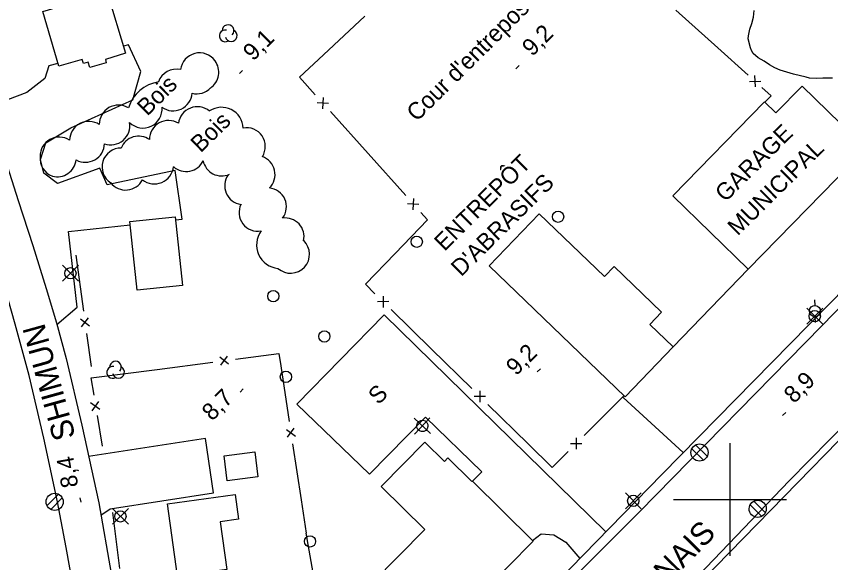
# Model space of a CAD drawing. Extents: x 381879 to 384696, y 5564785 to 5567594.
# Drawn here: x 383073.6 to 383217.8, y 5565788.8 to 5565885.6 of the extents above; entities that cross this region are included whole.
import ezdxf

# ---------------------------------------------------------------- set-up
doc = ezdxf.new("R2010")
doc.units = 0
for name, color, linetype in [('Niveau 1', 7, 'Continuous'), ('Niveau 19', 7, 'Continuous'), ('Niveau 21', 7, 'Continuous'), ('Niveau 22', 7, 'Continuous'), ('Niveau 3', 7, 'Continuous'), ('Niveau 31', 7, 'Continuous'), ('Niveau 36', 7, 'Continuous'), ('Niveau 37', 7, 'Continuous'), ('Niveau 44', 7, 'Continuous'), ('Niveau 52', 7, 'Continuous'), ('Niveau 57', 7, 'Continuous'), ('Niveau 61', 7, 'Continuous')]:
    doc.layers.add(name, color=color, linetype=linetype)

msp = doc.modelspace()

# ---------------------------------------------------------------- linework, layer by layer
at = {"layer": 'Niveau 1'}
msp.add_lwpolyline([(383218.14, 5565874.66), (383216.47, 5565874.7), (383215.25, 5565874.62), (383214.09, 5565874.7), (383213.49, 5565874.87), (383211.25, 5565875.41), (383208.91, 5565876.07), (383207.93, 5565876.49), (383207, 5565877.03), (383206.05, 5565877.7), (383204.99, 5565878.3), (383204.13, 5565879.06), (383203.81, 5565879.58), (383203.63, 5565880.05), (383203.23, 5565881.66), (383203.26, 5565882.19), (383203.53, 5565883.36), (383203.87, 5565884.34), (383204.17, 5565885.51), (383204.28, 5565886.66)], dxfattribs=at)
at = {"layer": 'Niveau 19'}
for points in [[(383101.78, 5565849.56), (383103, 5565849.69), (383101.74, 5565858.34), (383089.68, 5565855.78), (383088.39, 5565858.71), (383080.9, 5565855.98), (383078.47, 5565857.85), (383077.87, 5565860.26), (383078.84, 5565863.22), (383083.28, 5565865.88), (383094.22, 5565870.83), (383095.65, 5565875.88), (383093.49, 5565880.56), (383092.57, 5565880.32)], [(383080.98, 5565877.3), (383079.38, 5565876.88), (383078.66, 5565874.62), (383075.49, 5565872.15), (383072.04, 5565870.84), (383068.49, 5565869.87)], [(383080.77, 5565831.03), (383084.39, 5565834.08), (383082.86, 5565847.53), (383093.79, 5565848.7)], [(383203.21, 5565840.8), (383189.95, 5565827.06)], [(383181.1, 5565818.11), (383191.72, 5565808.31), (383191.72, 5565808.31)], [(383088.58, 5565797.23), (383090.24, 5565798.37), (383108.54, 5565801.18), (383107.11, 5565810.81), (383086.41, 5565807.65), (383086.41, 5565807.65)]]:
    msp.add_lwpolyline(points, dxfattribs=at)
at = {"layer": 'Niveau 21'}
for points in [[(383184, 5565797.8), (383216.28, 5565830.81), (383235.39, 5565850.47), (383275.62, 5565891.24), (383301.72, 5565917.97), (383337.3, 5565954.5), (383373.4, 5565991.3), (383408.2, 5566027), (383442.2, 5566061.7), (383475.8, 5566095.9)], [(383296.7, 5565891.1), (383280.8, 5565875), (383258.34, 5565852.55), (383246.6, 5565840.1), (383228.5, 5565821.6), (383210.51, 5565803.32), (383194.41, 5565786.56)], [(383067.06, 5565874.22), (383069.7, 5565866.2), (383073.9, 5565853), (383076.5, 5565845), (383078.9, 5565837.4), (383080.7, 5565831.3), (383082.4, 5565825), (383085.2, 5565813.2), (383088.2, 5565799.4), (383090.4, 5565786.9), (383093, 5565770), (383094.3, 5565760.4), (383096, 5565745.2), (383097.4, 5565731.2), (383098.3, 5565723.1), (383098.8, 5565719.9), (383099.7, 5565717.4), (383100.8, 5565715.9), (383101.9, 5565715.6)], [(383091, 5565706.2), (383090.4, 5565725), (383088.3, 5565748.4), (383085.9, 5565768.5), (383084.7, 5565777.6), (383083.7, 5565784.3), (383082.4, 5565791.5), (383080.9, 5565799.6), (383078.5, 5565810.9), (383075.9, 5565822), (383073.4, 5565831.1), (383070.89, 5565839.89)], [(383101.9, 5565715.6), (383103, 5565715.9), (383104.3, 5565716.6), (383105.6, 5565717.5), (383116.8, 5565728.8), (383135, 5565747.7), (383153.5, 5565766.7), (383172.3, 5565786.1), (383184, 5565797.8)]]:
    msp.add_lwpolyline(points, dxfattribs=at)
at = {"layer": 'Niveau 22'}
for points in [[(383156.53, 5565772.2), (383157.91, 5565773.63), (383187.98, 5565804.5), (383213.9, 5565830.88), (383244.88, 5565862.36), (383274.3, 5565892.74), (383302.87, 5565922), (383330.88, 5565950.51), (383359.91, 5565980.31), (383385.43, 5566006.36), (383414.56, 5566036.19)], [(383114.65, 5565703.59), (383143.11, 5565732.46), (383175.31, 5565765.37), (383202.42, 5565793.16), (383228.81, 5565820.22), (383246.73, 5565838.32)]]:
    msp.add_lwpolyline(points, dxfattribs=at)
at = {"layer": 'Niveau 3'}
for p, q in [((383113.12, 5565875.49), (383113.69, 5565876.06)), ((383162.1, 5565876.32), (383162.67, 5565876.89)), ((383165.86, 5565822.62), (383166.43, 5565823.19)), ((383113.22, 5565819.03), (383113.79, 5565819.6)), ((383209.3, 5565814.87), (383209.87, 5565815.44)), ((383085.06, 5565799.52), (383084.88, 5565800.3))]:
    msp.add_line(p, q, dxfattribs=at)
at = {"layer": 'Niveau 31'}
for points in [[(383078.31, 5565886.48), (383089.67, 5565889.91), (383092.94, 5565879.08), (383089.37, 5565878), (383089.54, 5565877.42), (383086.62, 5565876.56), (383086.34, 5565877.5), (383085.49, 5565877.25), (383085.27, 5565878.01), (383081.12, 5565876.8)], [(383224.12, 5565862.24), (383203.21, 5565840.8), (383189.87, 5565853.8), (383206.13, 5565870.48), (383208.14, 5565868.52), (383212.77, 5565873.24)], [(383101.72, 5565850.12), (383103.01, 5565837.96), (383095.02, 5565837.11), (383093.73, 5565849.27)], [(383181.44, 5565818.22), (383157.33, 5565841.4), (383166.2, 5565850.62), (383177.76, 5565839.5), (383179.47, 5565841.27), (383187.87, 5565833.19), (383185.8, 5565831.05), (383189.95, 5565827.06)], [(383110.39, 5565807.75), (383115.83, 5565808.44), (383116.39, 5565804.03), (383110.95, 5565803.34)], [(383102.12, 5565786.43), (383100.36, 5565799.24), (383112.37, 5565800.89), (383112.97, 5565796.5), (383109.7, 5565796.05), (383110.86, 5565787.63)]]:
    msp.add_lwpolyline(points, close=True, dxfattribs=at)
msp.add_lwpolyline([(383118.14, 5565766.54), (383145.96, 5565794.69), (383138.21, 5565802.34), (383145.97, 5565810.19), (383149.45, 5565806.75), (383150.06, 5565807.37), (383154.27, 5565803.21), (383154.35, 5565803.3), (383165.16, 5565792.62), (383156.3, 5565783.65)], dxfattribs=at)
at = {"layer": 'Niveau 36'}
for p, q in [((383084.61, 5565841.52), (383081.79, 5565838.7)), ((383084.61, 5565838.7), (383081.79, 5565841.52)), ((383214.99, 5565835.38), (383215.04, 5565834.38)), ((383216.44, 5565833.91), (383213.62, 5565831.09)), ((383216.44, 5565831.09), (383213.62, 5565833.91)), ((383215.14, 5565831.38), (383215.1, 5565832.38)), ((383144.04, 5565814.41), (383146.96, 5565811.69)), ((383144.14, 5565811.59), (383146.86, 5565814.51)), ((383195.96, 5565807.67), (383193.87, 5565809.68)), ((383193.24, 5565809.01), (383195.33, 5565807)), ((383081.09, 5565800.93), (383079.03, 5565798.89)), ((383184.3, 5565801.18), (383181.48, 5565798.36)), ((383184.3, 5565798.36), (383181.48, 5565801.18)), ((383079.69, 5565798.25), (383081.75, 5565800.29)), ((383206.27, 5565797.66), (383204.21, 5565799.71)), ((383093.46, 5565798.43), (383090.64, 5565795.61)), ((383093.46, 5565795.61), (383090.64, 5565798.43)), ((383203.57, 5565799.04), (383205.63, 5565796.99))]:
    msp.add_line(p, q, dxfattribs=at)
for centre, radius in [((383169.55, 5565850.11), 1), ((383144.52, 5565845.69), 1), ((383083.19, 5565840.11), 1), ((383119.12, 5565836.04), 1), ((383215.02, 5565832.5), 1), ((383128.16, 5565828.9), 1), ((383121.35, 5565821.75), 1), ((383080.4, 5565799.59), 1.52), ((383182.88, 5565799.77), 1), ((383092.04, 5565797.02), 1), ((383125.62, 5565792.58), 1)]:
    msp.add_circle(centre, radius, dxfattribs=at)
for centre, major_axis, ratio in [((383215.07, 5565833.39), (-0.05, -0.999), 0.999983), ((383145.51, 5565813.05), (0.871, -0.491), 0.999925), ((383194.6, 5565808.33), (0.01, 1.52), 0.999981), ((383204.92, 5565798.36), (-0.02, -1.52), 0.999984)]:
    msp.add_ellipse(centre, major_axis=major_axis, ratio=ratio, dxfattribs=at)
at = {"layer": 'Niveau 37'}
for p, q in [((383204.53, 5565873.12), (383204.43, 5565875.12)), ((383203.48, 5565874.07), (383205.48, 5565874.17)), ((383128.88, 5565870.18), (383126.88, 5565870.29)), ((383127.94, 5565871.23), (383127.83, 5565869.23)), ((383143.96, 5565853.37), (383143.85, 5565851.37)), ((383144.91, 5565852.31), (383142.91, 5565852.42)), ((383138.55, 5565836.07), (383138.56, 5565834.06)), ((383139.56, 5565835.07), (383137.55, 5565835.06)), ((383084.96, 5565832.02), (383086.55, 5565830.81)), ((383085.15, 5565830.61), (383086.36, 5565832.21)), ((383111.21, 5565824.02), (383109.62, 5565825.24)), ((383109.8, 5565823.84), (383111.03, 5565825.42)), ((383156.69, 5565818.27), (383154.69, 5565818.25)), ((383155.68, 5565819.26), (383155.7, 5565817.26)), ((383088.39, 5565815.98), (383086.76, 5565817.14)), ((383088.16, 5565817.37), (383086.99, 5565815.75)), ((383121.64, 5565811.03), (383122.83, 5565812.64)), ((383121.43, 5565812.43), (383123.04, 5565811.24)), ((383171.77, 5565809.92), (383173.77, 5565809.92)), ((383172.77, 5565810.92), (383172.77, 5565808.92))]:
    msp.add_line(p, q, dxfattribs=at)
for points in [[(383190.43, 5565886.72), (383197.86, 5565880.03)], [(383128.02, 5565878.81), (383135.32, 5565885.64)], [(383197.86, 5565880.03), (383203.24, 5565875.19)], [(383126.55, 5565871.72), (383123.76, 5565874.83), (383128.02, 5565878.81)], [(383205.62, 5565873.05), (383207.32, 5565871.52)], [(383207.32, 5565871.52), (383206.18, 5565870.44)], [(383135.9, 5565861.3), (383129.22, 5565868.74)], [(383142.57, 5565853.86), (383135.9, 5565861.3)], [(383140.69, 5565843.63), (383146.41, 5565849.58), (383145.24, 5565850.88)], [(383084.12, 5565843.3), (383085.48, 5565833.39)], [(383137.13, 5565836.47), (383135.42, 5565838.14), (383140.69, 5565843.63)], [(383147.12, 5565826.66), (383139.98, 5565833.66)], [(383086.03, 5565829.43), (383086.83, 5565823.58)], [(383112.4, 5565824.89), (383120.11, 5565825.9), (383120.44, 5565823.7)], [(383154.26, 5565819.66), (383147.12, 5565826.66)], [(383098.52, 5565823.07), (383108.43, 5565824.37)], [(383086.88, 5565821.56), (383098.52, 5565823.07)], [(383120.44, 5565823.7), (383121.94, 5565813.81)], [(383087.39, 5565818.49), (383086.88, 5565821.56)], [(383181.24, 5565818.42), (383174.18, 5565811.34)], [(383164.25, 5565809.85), (383157.12, 5565816.86)], [(383088.88, 5565809.45), (383087.98, 5565814.88)], [(383122.53, 5565809.86), (383124.03, 5565799.97)], [(383171.36, 5565808.5), (383168.53, 5565805.66), (383164.25, 5565809.85)], [(383124.03, 5565799.97), (383124.92, 5565794.06)], [(383090.64, 5565797.71), (383091.89, 5565787.79)], [(383125.84, 5565786.7), (383126.16, 5565787.02), (383124.92, 5565794.06)]]:
    msp.add_lwpolyline(points, dxfattribs=at)
at = {"layer": 'Niveau 44'}
for centre, radius, start, end in [((383106.05, 5565875.77), 3.39, 35.7798, 172.8412), ((383106.07, 5565875.73), 3.39, 304.1564, 36.5392), ((383099.78, 5565867.49), 6.6, 98.401, 163.0711), ((383101.37, 5565872.28), 3.39, 234.463, 355.2446), ((383091.7, 5565866.5), 3.4, 58.8593, 180.8216), ((383105.67, 5565866.24), 3.38, 50.64, 172.6031), ((383086.43, 5565863.61), 3.4, 56.6678, 178.616), ((383100.56, 5565863.8), 3.38, 58.527, 180.2865), ((383081.19, 5565860.84), 3.39, 57.1928, 180.4877), ((383085.82, 5565863.17), 3.4, 241.7226, 357.7888), ((383081.18, 5565860.48), 3.39, 174.4319, 249.6005), ((383080.84, 5565860.59), 3.39, 255.5556, 353.1946)]:
    msp.add_arc(centre, radius, start, end, dxfattribs=at)
for centre, major_axis, ratio, start_param, end_param in [((383110.61, 5565882.17), (0.912, -0.513), 0.999925, 1.88946, 5.776035), ((383111.1, 5565883.09), (0.912, -0.513), 0.999925, 6.029005, 9.968014), ((383111.65, 5565882.21), (0.912, -0.513), 0.999925, 3.902388, 7.872264), ((383101.97, 5565872.87), (-2.63, -2.15), 0.999984, 3.813936, 5.249276), ((383105.55, 5565875.29), (2.55, -2.23), 0.998821, 5.189852, 6.242587), ((383096.04, 5565869.22), (3.02, 1.52), 0.999984, 3.468054, 5.908773), ((383109.95, 5565865.7), (1.73, 3.4), 0.998988, 5.21922, 7.347395), ((383090.33, 5565866.24), (2.44, 2.34), 0.999984, 3.607648, 5.689844), ((383114.35, 5565862.54), (2.01, 2.7), 0.993342, 4.790228, 7.10288), ((383095.27, 5565861.03), (-2.99, -1.53), 0.999936, 3.633464, 5.424059), ((383092.14, 5565858.94), (0.5, -3.32), 0.999418, 2.985728, 5.559884), ((383116.08, 5565857.6), (2.17, 2.56), 0.998035, 4.623172, 6.656808), ((383098.03, 5565859.36), (1.33, -3.16), 0.999994, 5.222201, 7.347295), ((383103.68, 5565861.5), (3.15, 1.15), 0.999984, 3.633698, 5.48711), ((383109.97, 5565860.71), (2.66, -2.05), 0.999418, 3.99804, 5.786675), ((383113.87, 5565855.61), (3.34, -0.34), 0.997682, 2.629957, 4.668288), ((383092.95, 5565858.21), (3.36, 0.05), 0.999984, 3.799424, 5.787669), ((383118.12, 5565851.9), (3.05, 1.33), 0.999947, 5.221628, 7.349305), ((383116.39, 5565850.89), (-1.71, -2.88), 0.996961, 4.788451, 6.99683), ((383121.22, 5565846.56), (-1.95, 2.72), 0.999427, 3.883888, 5.793503), ((383120.31, 5565845.11), (-3.79, -1.71), 0.998484, 5.21759, 7.34247), ((383122.18, 5565843.47), (3.15, 1.16), 0.999984, 3.632593, 6.735244), ((383091.16, 5565823.46), (0.912, -0.513), 0.999925, 6.029005, 9.968014), ((383090.67, 5565822.54), (0.912, -0.513), 0.999925, 1.88946, 5.776035), ((383091.71, 5565822.58), (0.912, -0.513), 0.999925, 3.902388, 7.872264)]:
    msp.add_ellipse(centre, major_axis=major_axis, ratio=ratio, start_param=start_param, end_param=end_param, dxfattribs=at)
at = {"layer": 'Niveau 52'}
for points in [[(383178.02, 5565794.27), (383138.77, 5565832.72), (383123.3, 5565816.91), (383136.15, 5565804.48), (383146.07, 5565814.6), (383156.04, 5565804.91), (383154.42, 5565803.23)], [(383165.05, 5565792.73), (383166.57, 5565793.93), (383168.79, 5565793.74), (383170.93, 5565792.43), (383173.44, 5565789.57)]]:
    msp.add_lwpolyline(points, dxfattribs=at)
at = {"layer": 'Niveau 61'}
for points in [[(383200, 5565810), (383200, 5565800), (383200, 5565790)], [(383190, 5565800), (383200, 5565800), (383210, 5565800)]]:
    msp.add_lwpolyline(points, dxfattribs=at)

# ---------------------------------------------------------------- texts
at = {"layer": 'Niveau 21'}
for s, rotation, p in [('SHIMUN', 105.5122, (383084.14, 5565811.12)), ('BOULEVARD DES MONTAGNAIS', 45.5594, (383139.65, 5565734.63))]:
    msp.add_text(s, height=4, rotation=rotation, dxfattribs=at).set_placement(p)
at = {"layer": 'Niveau 3'}
for s, rotation, p in [('9,2', 44.7717, (383164.98, 5565878.41)), ('9,1', 44.7717, (383115.55, 5565877.59)), ('9,2  ', 44.7717, (383162.13, 5565821.82)), ('8,9  ', 44.7717, (383211.35, 5565816.9)), ('8,7', 44.7717, (383108.27, 5565813.8)), ('8,4  ', 100.0243, (383084.6, 5565802.36))]:
    msp.add_text(s, height=3, rotation=rotation, dxfattribs=at).set_placement(p)
at = {"layer": 'Niveau 31'}
for s, p in [('GARAGE', (383199.17, 5565852.58)), ('MUNICIPAL', (383201.37, 5565846.6)), ('ENTREPÔT', (383149.42, 5565843.87)), ("D'ABRASIFS", (383152.39, 5565839.36))]:
    msp.add_text(s, height=3, rotation=44.7717, dxfattribs=at).set_placement(p)
at = {"layer": 'Niveau 44'}
for p in [(383096.79, 5565867.84), (383106.27, 5565861.34)]:
    msp.add_text('Bois', height=3, rotation=44.7707, dxfattribs=at).set_placement(p)
at = {"layer": 'Niveau 52'}
msp.add_text('S', height=3, rotation=44.7717, dxfattribs=at).set_placement((383137.73, 5565816.66))
at = {"layer": 'Niveau 57'}
msp.add_text("Cour d'entreposage", height=3, rotation=44.7717, dxfattribs=at).set_placement((383144.52, 5565866.84))

doc.saveas('drawing.dxf')
